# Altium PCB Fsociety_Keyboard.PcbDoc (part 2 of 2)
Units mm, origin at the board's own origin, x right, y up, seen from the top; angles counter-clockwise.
Board outline 368.7 x 110 mm, 2 copper layers (Top Layer, Bottom Layer), stack 1.601 mm thick; 249 components, 201 nets, 1088 pads, 275 vias.
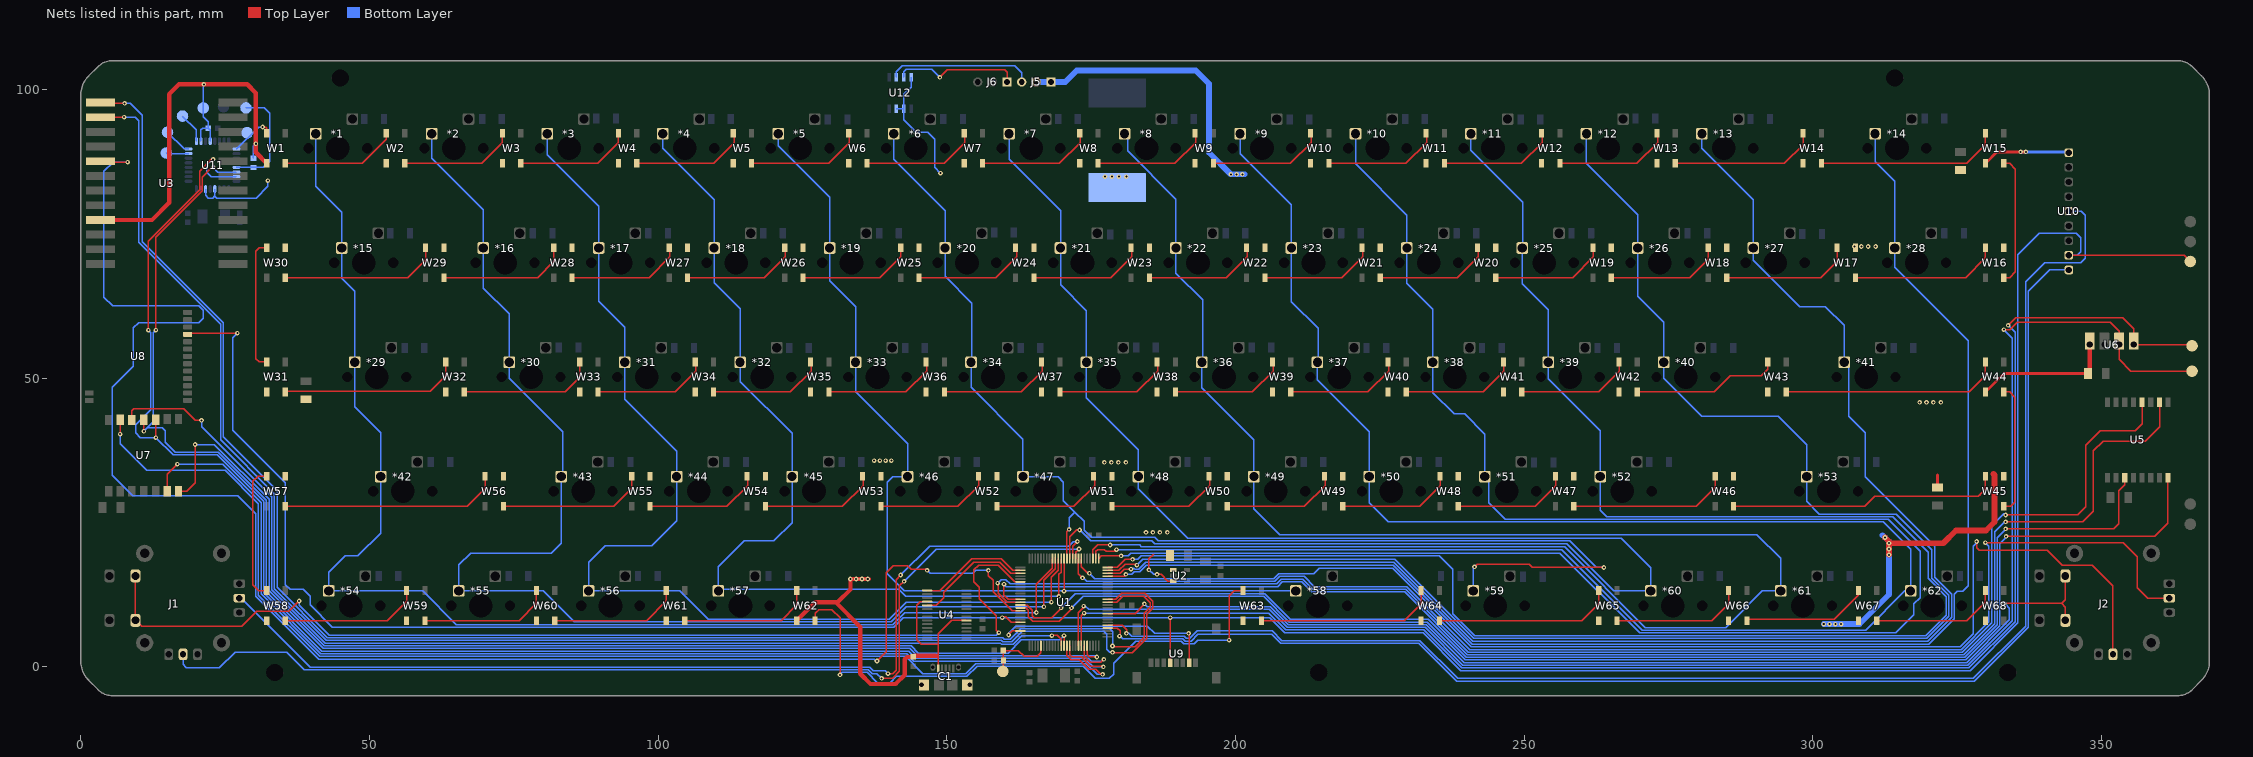
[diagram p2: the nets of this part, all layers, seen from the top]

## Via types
v1: diameter 0.8, hole 0.35, Top Layer to Bottom Layer, tented both sides, 275 vias

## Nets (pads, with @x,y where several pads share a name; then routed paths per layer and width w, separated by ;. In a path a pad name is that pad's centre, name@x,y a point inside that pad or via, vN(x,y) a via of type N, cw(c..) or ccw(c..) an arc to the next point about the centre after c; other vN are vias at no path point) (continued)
NetJ1_2: J1.2 U1.85 | length 172.5
  Top Layer w0.254: v1(139.8,-1.2) 140.6,-1.2 141.2,-0.6 141.2,15.1 v1(142,15.9) ; U1.85@171.8,18.75 171.8,20.9 v1(172.6,21.7)
  Bottom Layer w0.254: J1.2@27.45,11.9 27.8,11.9 39.771,-0.071 136.629,-0.071 137.258,-0.7 139.3,-0.7 v1(139.8,-1.2) ; v1(142,15.9) 147,20.9 171.1,20.9 171.9,21.7 v1(172.6,21.7)
NetJ1_5: J1.5 U1.84 | length 180.1
  Top Layer w0.254: v1(138.7,-2) 140.6,-2 141.8,-0.8 141.8,14 v1(142.6,14.8) ; U1.84@172.3,18.75 172.3,19.8 v1(172.9,20.4)
  Bottom Layer w0.254: J1.5@17.7,2.15 17.7,0.4 18.2,-0.1 18.2,-0.2 24,-0.2 26.7,2.5 35.7,2.5 38.725,-0.525 136.425,-0.525 137.1,-1.2 137.9,-1.2 v1(138.7,-2) ; v1(142.6,14.8) 148.2,20.4 v1(172.9,20.4)
NetJ2_2: J2.2 U1.83 | length 221.4
  Top Layer w0.254: U1.83@172.8,18.75 172.8,16.1 v1(173.5,15.4) v1@173.6,15.3 ; v1(329.9,21.5) 353.8,21.5 356.2,19.1 356.2,13.7 358,11.9 J2.2@361.75,11.9
  Bottom Layer w0.254: v1(173.5,15.4) 173.608,15.4 174.2,14.808 206.8,14.808 207.646,15.654 211.9,15.654 213.654,13.9 229.7,13.9 240.608,2.992 325.734,2.992 330.5,7.758 330.5,20.9 v1@330,21.4
NetJ2_5: J2.5 U1.82 | length 219.7
  Top Layer w0.254: U1.82@173.3,18.75 173.3,17.3 174.4,16.2 v1(174.7,16.2) v1@174.8,16.1 ; v1(328.4,21.7) 328.4,20.6 328.8,20.2 340.6,20.2 343.2,17.6 348.4,17.6 352,14 J2.5@352,2.15
  Bottom Layer w0.254: v1(174.7,16.2) 175.638,15.262 206.612,15.262 207.458,16.108 213.562,16.108 214.481,17.027 227.231,17.027 240.812,3.446 325.546,3.446 327.8,5.7 327.8,20.9 v1@328.5,21.6
NetJ2_7: J2.7 U1.59 | length 185.5
  Top Layer w0.254: U1.59@177.85,9.2 182.6,9.2 184.2,10.8 v1@184.3,10.8 ; v1(333.2,11) 343.1,11 ; J2.7@343.75,8.05 343.75,10.35 343.1,11 ; J2.7@343.75,15.75 343.75,11.65 343.1,11
  Bottom Layer w0.254: v1(184.2,10.9) 184.7,10.4 206.016,10.4 209.124,7.292 233.018,7.292 239.588,0.722 326.674,0.722 334.076,8.124 334.076,10.124 v1@333.3,10.9
NetJ5_3: J5.3 U12.6 | length 25.2
  Bottom Layer w0.254: U12.6@141.265,102.125 141.265,103.065 142.3,104.1 161.8,104.1 162.968,102.932 J5.3@162.968,101.3
NetJ6_1: J6.1 U12.7 | length 22
  Top Layer w0.254: v1(148.8,102.1) 150.1,103.4 160,103.4 160.44,102.96 J6.1@160.44,101.3
  Bottom Layer w0.254: U12.7@142.535,102.125 142.535,103.035 143,103.5 147.4,103.5 v1(148.8,102.1)
NetR2_2: R2.2 TP9.1 U11.29 | length 19
  Bottom Layer w0.254: U11.29@26.95,86.5 R2.2@29.9,86.5 31.6,86.5 32.7,87.6 32.7,95.9 31.8,96.8 TP9.1@28.6,96.8
NetTP10_1: TP10.1 U11.15 | length 3.9
  Bottom Layer w0.254: TP10.1@14.8,89 14.9,88.9 U11.15@18.65,88.9
NetTP11_1: TP11.1 U11.16 | length 4.9
  Bottom Layer w0.254: TP11.1@15,92.6 17.9,89.7 U11.16@18.65,89.7
NetTP12_1: TP12.1 U11.17 | length 5.3
  Bottom Layer w0.254: TP12.1@17.6,95.4 20,93 U11.17@20,91.05
NetTP13_1: TP13.1 U11.25 W1.4 | length 7.8
  Top Layer w0.254: v1(31.5,93.5) 32,93.5 32.21,93.29 W1.4@32.21,92.4
  Bottom Layer w0.254: U11.25@26.95,89.7 27,89.7 30.8,93.5 v1(31.5,93.5)
NetTP14_1: TP14.1 U1.43 U6.3 | length 265.9
  Top Layer w0.254: U1.43@172.8,3.65 172.8,9.4 v1@173.8,10.4 ; v1(333.1,58.4) 334.128,58.4 335.428,59.7 351.5,59.7 353.065,58.135 U6.3@353.065,55.825 353.065,53.235 355.1,51.2 TP14.1@365.7,51.2
  Bottom Layer w0.254: v1(173.7,10.5) 174,10.5 174.554,9.946 205.828,9.946 208.936,6.838 232.83,6.838 239.4,0.268 326.862,0.268 334.591,7.997 334.591,56.909 v1@333.2,58.3
NetTP15_1: TP15.1 U1.44 U6.4 | length 262.1
  Top Layer w0.254: U1.44@173.3,3.65 173.3,8.8 v1(173.8,9.3) ; v1(333.85,59.15) 335.2,60.5 353.7,60.5 355.605,58.595 U6.4@355.605,55.825 365.475,55.825 TP15.1@365.7,55.6
  Bottom Layer w0.254: v1(173.8,9.3) 205.8,9.3 208.716,6.384 232.642,6.384 239.212,-0.186 327.05,-0.186 335.045,7.809 335.045,57.955 v1@333.95,59.05
NetU1_2: U1.2 U4.1 | length 19.3
  Top Layer w0.254: U4.1@146.6,13.225 146.625,13.2 148.8,13.2 154.3,18.7 159.4,18.7 161.4,16.7 U1.2@162.75,16.7
NetU1_3: U1.3 U4.5 | length 20.6
  Top Layer w0.254: U4.5@146.6,10.625 148.125,10.625 149.5,12 149.5,12.9 154.7,18.1 159.2,18.1 161.1,16.2 U1.3@162.75,16.2
NetU1_12: U1.12 U5.2 | length 247.1
  Top Layer w0.254: v1@159.9,14.2 159.9,12.4 160.6,11.7 U1.12@162.75,11.7 ; v1(333.4,25.1) 346.8,25.1 348.6,26.9 348.6,37.4 350.3,39.1 357.6,39.1 360.1,41.6 U5.2@360.1,45.84
  Bottom Layer w0.254: v1(159.9,14.3) 160.3,13.9 207.3,13.9 208.1,14.7 211.5,14.7 213.244,12.956 213.265,12.977 229.281,12.977 240.174,2.084 326.11,2.084 331.492,7.466 331.492,23.392 v1@333.4,25.3
NetU1_13: U1.13 U5.4 | length 247
  Top Layer w0.254: v1@158.9,14.4 158.9,12.758 160.458,11.2 U1.13@162.75,11.2 ; v1(333.4,26.3) 345.9,26.3 347.3,27.7 347.3,38.4 349.8,40.9 355.9,40.9 357.1,42.1 U5.4@357.1,45.84
  Bottom Layer w0.254: v1(158.8,14.5) 159.4,15.1 160.2,15.1 160.946,14.354 207.112,14.354 207.958,15.2 211.642,15.2 213.396,13.446 229.454,13.446 240.362,2.538 325.922,2.538 331.038,7.654 331.038,24.438 333.1,26.5 v1@333.5,26.5
NetU1_14: U1.14 U5.11 | length 225
  Top Layer w0.254: U1.14@162.75,10.7 163.9,10.7 164.773,9.827 164.773,8.827 165.1,8.5 168.2,8.5 169.8,10.1 v1@169.9,10.1 ; v1(333.4,23.9) 352.1,23.9 353,24.8 353,30.5 354.05,31.55 U5.11@354.05,32.76
  Bottom Layer w0.254: v1(169.8,10.2) 172.254,12.654 205.046,12.654 209.5,8.2 233.4,8.2 239.97,1.63 326.298,1.63 331.946,7.278 331.946,22.346 v1@333.5,23.9
NetU1_15: U1.15 U5.16 | length 232.8
  Top Layer w0.254: U1.15@162.75,10.2 163.675,10.2 164.1,9.775 164.1,8.7 164.9,7.9 169.5,7.9 v1@171.7,10.1 ; v1(333.5,22.6) 359.2,22.6 361.5,24.9 U5.16@361.5,32.76
  Bottom Layer w0.254: v1(171.6,10.2) 173.6,12.2 204.858,12.2 209.312,7.746 233.212,7.746 239.782,1.176 326.486,1.176 332.4,7.09 332.4,21.3 v1@333.6,22.5
NetU1_23: U1.23 U9.2 | length 39.9
  Top Layer w0.254: v1@160.7,5.6 161.3,6.2 U1.23@162.75,6.2 ; v1(191.9,5.8) 191.975,5.725 U9.2@191.975,0.725
  Bottom Layer w0.254: v1(160.7,5.5) v1(160.7,5.5) 160.7,5.8 161.946,7.046 184.754,7.046 186,5.8 v1(191.9,5.8)
NetU1_37: U1.37 U7.12 | length 191.5
  Top Layer w0.254: U7.12@8.829,42.744 8.829,44.329 9.2,44.7 17.8,44.7 19.8,42.7 v1(20.9,42.7) ; v1@168.392,5.492 169.1,5.492 169.8,4.792 U1.37@169.8,3.65
  Bottom Layer w0.254: v1(20.9,42.7) 20.9,41.6 33.076,29.424 33.076,13.372 42.348,4.1 159.258,4.1 159.493,3.865 161.465,3.865 163,5.4 v1(168.2,5.4)
NetU1_38: U1.38 U7.7 | length 187.8
  Top Layer w0.254: U7.7@16.918,30.399 18.299,30.399 19.8,31.9 v1(19.8,38.5) ; U1.38@170.3,3.65 v1(170.3,5.4)
  Bottom Layer w0.254: v1(19.8,38.5) 23.122,38.5 32.6,29.022 32.6,13.2 42.154,3.646 143.8,3.646 145.073,2.373 160.615,2.373 162.915,4.673 169.573,4.673 v1(170.3,5.4)
NetU1_39: U1.39 U7.13 | length 211
  Top Layer w0.254: v1(6.8,40.3) 6.816,40.316 U7.13@6.816,42.794 ; U1.39@170.8,3.65 170.8,1.958 171.512,1.246 172.954,1.246 174.6,-0.4 175.8,-0.4 176.7,-1.3 v1(177,-1.3) v1@177.1,-1.3
  Bottom Layer w0.254: v1(6.8,40.3) 6.8,38.6 11.4,34 25,34 30.746,28.254 30.746,12.432 41.386,1.792 142.866,1.792 145.858,-1.2 153.3,-1.2 155.046,0.546 174.17,0.546 176.016,-1.3 v1(177,-1.3)
NetU1_40: U1.40 U7.6 | length 197.8
  Top Layer w0.254: U7.6@14.951,30.399 14.951,33.351 v1(16.7,35.1) ; U1.40@171.3,3.65 171.3,2.1 171.7,1.7 173.258,1.7 174.858,0.1 v1@177.1,0.1
  Bottom Layer w0.254: v1(16.7,35.1) 24.542,35.1 31.2,28.442 31.2,12.62 41.574,2.246 143.054,2.246 144.3,1 174.358,1 175.358,0 v1(177.1,0)
NetU1_63: U1.63 U3.0 | length 272.2
  Top Layer w0.254: U3.0@3.425,97.725 3.55,97.6 v1(7.594,97.6) ; U1.63@177.85,11.2 179.442,11.2 180.442,12.2 184.1,12.2 185.2,11.1 185.2,10.3 184.2,9.3 184.2,5.1 182.6,3.5 v1@178.8,3.5
  Bottom Layer w0.254: v1(7.594,97.6) 8.575,97.6 10.6,95.575 10.6,73.6 24.646,59.554 24.646,39.854 33.984,30.516 33.984,13.748 42.687,5.045 159.655,5.045 159.927,4.773 161.001,4.773 162.82,6.592 178.208,6.592 178.7,6.1 v1(178.7,3.6)
NetU1_64: U1.64 U3.1 | length 272.9
  Top Layer w0.254: U3.1@3.425,95.185 3.44,95.2 v1(7.5,95.2) ; U1.64@177.85,11.7 179.3,11.7 180.3,12.7 184.3,12.7 185.654,11.346 185.654,10.112 184.654,9.112 184.654,4.912 182.142,2.4 v1@178.8,2.4
  Bottom Layer w0.254: v1(7.5,95.2) 9.4,95.2 10.052,94.548 10.052,73.506 24.192,59.366 24.192,39.308 33.53,29.97 33.53,13.56 42.499,4.591 159.409,4.591 159.681,4.319 161.219,4.319 163.038,6.138 177.162,6.138 177.7,5.6 177.7,3 178.2,2.5 v1(178.7,2.5)
NetW1_2: W1.2 W2.4 | length 20.3
  Top Layer w0.254: W1.2@35.39,87.2 48.715,87.2 52.91,91.395 W2.4@52.91,92.4
NetW2_2: W2.2 W3.4 | length 20
  Top Layer w0.254: W2.2@56.09,87.2 69.415,87.2 73,90.785 W3.4@73,92.4
NetW3_2: W3.2 W4.4 | length 20
  Top Layer w0.254: W3.2@76.19,87.2 89.515,87.2 93.11,90.795 W4.4@93.11,92.4
NetW4_2: W4.2 W5.4 | length 20
  Top Layer w0.254: W4.2@96.29,87.2 109.615,87.2 113.21,90.795 W5.4@113.21,92.4
NetW5_2: W5.2 W6.4 | length 20
  Top Layer w0.254: W5.2@116.19,87.2 129.515,87.2 133.11,90.795 W6.4@133.11,92.4
NetW6_2: W6.2 W7.4 | length 20
  Top Layer w0.254: W6.2@136.19,87.2 149.515,87.2 153.11,90.795 W7.4@153.11,92.4
NetW7_2: W7.2 W8.4 | length 20
  Top Layer w0.254: W7.2@156.19,87.2 169.515,87.2 173.11,90.795 W8.4@173.11,92.4
NetW8_2: W8.2 W9.4 | length 20
  Top Layer w0.254: W8.2@176.19,87.2 189.515,87.2 193.11,90.795 W9.4@193.11,92.4
NetW9_2: W9.2 W10.4 | length 20
  Top Layer w0.254: W9.2@196.19,87.2 209.515,87.2 213.11,90.795 W10.4@213.11,92.4
NetW10_2: W10.2 W11.4 | length 20
  Top Layer w0.254: W10.2@216.19,87.2 229.515,87.2 233.11,90.795 W11.4@233.11,92.4
NetW11_2: W11.2 W12.4 | length 20
  Top Layer w0.254: W11.2@236.19,87.2 249.515,87.2 253.11,90.795 W12.4@253.11,92.4
NetW12_2: W12.2 W13.4 | length 20
  Top Layer w0.254: W12.2@256.19,87.2 269.515,87.2 273.11,90.795 W13.4@273.11,92.4
NetW13_2: W13.2 W14.4 | length 25.4
  Top Layer w0.254: W13.2@276.19,87.2 295.1,87.2 298.31,90.41 W14.4@298.31,92.4
NetW14_2: W14.2 W15.4 | length 31.7
  Top Layer w0.254: W14.2@301.49,87.2 326.7,87.2 329.91,90.41 W15.4@329.91,92.4
NetW15_2: W15.2 W16.4 | length 22.6
  Top Layer w0.254: W16.4@333.09,67.4 334.1,67.4 335.1,68.4 335.1,86.2 334.1,87.2 W15.2@333.09,87.2
NetW16_2: W16.2 W17.4 | length 25.7
  Top Layer w0.254: W17.4@307.39,67.4 326.5,67.4 329.91,70.81 W16.2@329.91,72.6
NetW17_2: W17.2 W18.4 | length 22.7
  Top Layer w0.254: W18.4@285.09,67.4 301.4,67.4 304.21,70.21 W17.2@304.21,72.6
NetW18_2: W18.2 W19.4 | length 20.1
  Top Layer w0.254: W19.4@265.09,67.4 278.7,67.4 281.91,70.61 W18.2@281.91,72.6
NetW19_2: W19.2 W20.4 | length 20.1
  Top Layer w0.254: W20.4@245.09,67.4 258.415,67.4 262.01,70.995 262.01,72.5 W19.2@261.91,72.6
NetW20_2: W20.2 W21.4 | length 20
  Top Layer w0.254: W21.4@225.09,67.4 238.415,67.4 242.01,70.995 W20.2@242.01,72.6
NetW21_2: W21.2 W22.4 | length 20
  Top Layer w0.254: W22.4@205.09,67.4 218.415,67.4 222.01,70.995 W21.2@222.01,72.6
NetW22_2: W22.2 W23.4 | length 20
  Top Layer w0.254: W23.4@185.09,67.4 198.415,67.4 202.01,70.995 W22.2@202.01,72.6
NetW23_2: W23.2 W24.4 | length 20
  Top Layer w0.254: W24.4@165.09,67.4 178.415,67.4 182.01,70.995 W23.2@182.01,72.6
NetW24_2: W24.2 W25.4 | length 20
  Top Layer w0.254: W25.4@145.19,67.4 158.515,67.4 162.11,70.995 W24.2@162.11,72.6
NetW25_2: W25.2 W26.4 | length 20
  Top Layer w0.254: W26.4@125.09,67.4 138.415,67.4 142.01,70.995 W25.2@142.01,72.6
NetW26_2: W26.2 W27.4 | length 20
  Top Layer w0.254: W27.4@105.09,67.4 118.415,67.4 122.01,70.995 W26.2@122.01,72.6
NetW27_2: W27.2 W28.4 | length 20
  Top Layer w0.254: W28.4@85.09,67.4 98.415,67.4 102.01,70.995 W27.2@102.01,72.6
NetW28_2: W28.2 W29.4 | length 22.6
  Top Layer w0.254: W29.4@62.89,67.4 79.1,67.4 81.91,70.21 W28.2@81.91,72.6
NetW29_2: W29.2 W30.4 | length 27.7
  Top Layer w0.254: W30.4@35.39,67.4 56.6,67.4 59.71,70.51 W29.2@59.71,72.6
NetW30_2: W30.2 W31.4 | length 22.9
  Top Layer w0.254: W31.4@32.21,52.8 30.9,52.8 30.3,53.4 30.3,72 30.9,72.6 W30.2@32.21,72.6
NetW31_2: W31.2 W32.4 | length 31.4
  Top Layer w0.254: W31.2@35.39,47.6 35.49,47.7 60.5,47.7 63.21,50.41 W32.4@63.21,52.8
NetW32_2: W32.2 W33.4 | length 23.7
  Top Layer w0.254: W32.2@66.39,47.6 83.9,47.6 86.41,50.11 W33.4@86.41,52.8
NetW33_2: W33.2 W34.4 | length 20
  Top Layer w0.254: W33.2@89.59,47.6 102.915,47.6 106.51,51.195 W34.4@106.51,52.8
NetW34_2: W34.2 W35.4 | length 20
  Top Layer w0.254: W34.2@109.59,47.6 122.915,47.6 126.51,51.195 W35.4@126.51,52.8
NetW35_2: W35.2 W36.4 | length 20
  Top Layer w0.254: W35.2@129.59,47.6 142.915,47.6 146.51,51.195 W36.4@146.51,52.8
NetW36_2: W36.2 W37.4 | length 20
  Top Layer w0.254: W36.2@149.59,47.6 162.915,47.6 166.51,51.195 W37.4@166.51,52.8
NetW37_2: W37.2 W38.4 | length 20
  Top Layer w0.254: W37.2@169.59,47.6 182.915,47.6 186.51,51.195 W38.4@186.51,52.8
NetW38_2: W38.2 W39.4 | length 20
  Top Layer w0.254: W38.2@189.59,47.6 202.915,47.6 206.51,51.195 W39.4@206.51,52.8
NetW39_2: W39.2 W40.4 | length 20
  Top Layer w0.254: W39.2@209.59,47.6 222.915,47.6 226.51,51.195 W40.4@226.51,52.8
NetW40_2: W40.2 W41.4 | length 20
  Top Layer w0.254: W40.2@229.59,47.6 242.915,47.6 246.51,51.195 W41.4@246.51,52.8
NetW41_2: W41.2 W42.4 | length 20
  Top Layer w0.254: W41.2@249.59,47.6 262.915,47.6 266.51,51.195 W42.4@266.51,52.8
NetW42_2: W42.2 W43.4 | length 25.5
  Top Layer w0.254: W42.2@269.59,47.6 282.915,47.6 285.715,50.4 291.1,50.4 292.21,51.51 W43.4@292.21,52.8
NetW43_2: W43.2 W44.4 | length 38.1
  Top Layer w0.254: W43.2@295.39,47.6 327.1,47.6 329.91,50.41 W44.4@329.91,52.8
NetW44_2: W44.2 W45.4 | length 22.7
  Top Layer w0.254: W45.4@333.09,27.8 334.3,27.8 335,28.5 335,46.7 334.1,47.6 W44.2@333.09,47.6
NetW45_2: W45.2 W46.4 | length 47.5
  Top Layer w0.254: W46.4@286.29,27.8 309,27.8 310.7,29.5 328.7,29.5 ; 329,29.8 328.7,29.5 ; W45.2@329.91,33 329.91,30.71 328.7,29.5
NetW46_2: W46.2 W47.4 | length 27.8
  Top Layer w0.254: W47.4@258.59,27.8 279.8,27.8 283.11,31.11 W46.2@283.11,33
NetW47_2: W47.2 W48.4 | length 20
  Top Layer w0.254: W48.4@238.59,27.8 251.915,27.8 255.51,31.395 W47.2@255.51,33
NetW48_2: W48.2 W49.4 | length 20
  Top Layer w0.254: W49.4@218.59,27.8 231.915,27.8 235.51,31.395 W48.2@235.51,33
NetW49_2: W49.2 W50.4 | length 20
  Top Layer w0.254: W50.4@198.59,27.8 211.915,27.8 215.51,31.395 W49.2@215.51,33
NetW50_2: W50.2 W51.4 | length 20
  Top Layer w0.254: W51.4@178.59,27.8 191.915,27.8 195.51,31.395 W50.2@195.51,33
NetW51_2: W51.2 W52.4 | length 20
  Top Layer w0.254: W52.4@158.69,27.8 172.015,27.8 175.61,31.395 W51.2@175.61,33
NetW52_2: W52.2 W53.4 | length 20
  Top Layer w0.254: W53.4@138.59,27.8 151.915,27.8 155.51,31.395 W52.2@155.51,33
NetW53_2: W53.2 W54.4 | length 20
  Top Layer w0.254: W54.4@118.59,27.8 131.915,27.8 135.51,31.395 W53.2@135.51,33
NetW54_2: W54.2 W55.4 | length 20.1
  Top Layer w0.254: W55.4@98.59,27.8 111.915,27.8 115.51,31.395 115.51,32.9 W54.2@115.41,33
NetW55_2: W55.2 W56.4 | length 25.6
  Top Layer w0.254: W56.4@73.19,27.8 92.3,27.8 95.41,30.91 W55.2@95.41,33
NetW56_2: W56.2 W57.4 | length 38
  Top Layer w0.254: W57.4@35.39,27.8 66.9,27.8 70.01,30.91 W56.2@70.01,33
NetW57_2: W57.2 W58.4 | length 23.5
  Top Layer w0.254: W58.4@32.21,13.2 30.8,13.2 29.8,14.2 29.8,32.1 30.7,33 W57.2@32.21,33
NetW58_2: W58.2 W59.4 | length 24.3
  Top Layer w0.254: W58.2@35.39,8 53.1,8 56.41,11.31 W59.4@56.41,13.2
NetW59_2: W59.2 W60.4 | length 22.8
  Top Layer w0.254: W59.2@59.59,8 75.9,8 78.91,11.01 W60.4@78.91,13.2
NetW60_2: W60.2 W61.4 | length 22.5
  Top Layer w0.254: W60.2@82.09,8 98,8 101.41,11.41 W61.4@101.41,13.2
NetW61_2: W61.2 W62.4 | length 23
  Top Layer w0.254: W61.2@104.59,8 121.3,8 124.01,10.71 W62.4@124.01,13.2
NetW62_2: W62.2 W63.4 | length 101.3
  Top Layer w0.254: W62.2@127.19,8 127.19,9.29 127.8,9.9 130.1,9.9 131.5,8.5 v1(131.5,-1.4) ; v1(198.9,4.6) 198.9,12.3 199.8,13.2 W63.4@201.31,13.2
  Bottom Layer w0.254: v1(131.5,-1.4) 131.921,-0.979 136.179,-0.979 137.927,-2.727 140.173,-2.727 141.246,-1.654 153.488,-1.654 155.234,0.092 173.608,0.092 175.727,-2.027 178.173,-2.027 178.9,-1.3 178.9,0.6 182.692,4.392 190.6,4.392 191,3.992 192.892,3.992 193.5,4.6 v1(198.9,4.6)
NetW63_2: W63.2 W64.4 | length 31.1
  Top Layer w0.254: W63.2@204.49,8 229.2,8 232.16,10.96 W64.4@232.16,13.2
NetW64_2: W64.2 W65.4 | length 31.1
  Top Layer w0.254: W64.2@235.34,8 260,8 262.91,10.91 W65.4@262.91,13.2
NetW65_2: W65.2 W66.4 | length 22.8
  Top Layer w0.254: W65.2@266.09,8 282.5,8 285.41,10.91 W66.4@285.41,13.2
NetW66_2: W66.2 W67.4 | length 21.9
  Top Layer w0.254: W66.2@288.59,8 288.79,8.2 303.7,8.2 307.91,12.41 W67.4@307.91,13.2
NetW67_2: W67.2 W68.4 | length 22.1
  Top Layer w0.254: W67.2@311.09,8 326.7,8 329.91,11.21 W68.4@329.91,13.2
NewNet1: C1.@153.975,-3.127 C1.Z6
NewNet2: C1.@145.625,-3.127 C1.Z3
NFCCS: U1.54 U10.1 | length 235.6
  Top Layer w0.254: U1.54@177.85,6.7 179.5,6.7 180,6.2 v1@180,5.2
  Bottom Layer w0.254: v1(179.9,5.3) 180,5.3 180.454,4.846 190.9,4.846 191.3,4.446 192.346,4.446 193.5,5.6 206.29,5.6 207.806,4.084 231.732,4.084 238.286,-2.47 327.996,-2.47 337.315,6.849 337.315,65.015 341.04,68.74 U10.1@344.35,68.74
NFCIRQ: U1.55 U10.5 | length 250.2
  Top Layer w0.254: U1.55@177.85,7.2 180.4,7.2 181.2,6.4 v1@181.2,5.7
  Bottom Layer w0.254: v1@181.392,5.9 181.992,5.3 191.1,5.3 191.5,4.9 192.1,4.9 193.4,6.2 206.332,6.2 207.994,4.538 231.92,4.538 238.474,-2.016 327.808,-2.016 336.861,7.037 336.861,66.661 340.2,70 346.4,70 347.2,70.8 347.2,78.2 346.5,78.9 U10.5@344.35,78.9
  other v1: 181.1,5.8
PAIRHID: U1.16 U3.4 | length 290
  Top Layer w0.254: U3.4@3.425,87.565 3.59,87.4 v1(8.1,87.4) ; v1(137.9,1) 139.546,2.646 139.546,16.33 140.751,17.535 143.165,17.535 143.8,16.9 146.4,16.9 v1(146.6,16.7) ; v1(157.2,16.7) 157.2,15.8 158,15 158,13 161.3,9.7 U1.16@162.75,9.7
  Bottom Layer w0.254: v1@8,87.6 8,87.4 5.6,87.4 4,85.8 4,64 5.5,62.5 20.416,62.5 21.2,61.716 21.2,60.4 20.4,59.6 10,59.6 9.1,58.7 9.1,52.1 5.4,48.4 5.4,33.2 8.98,29.62 27.181,29.62 30.292,26.509 30.292,12.244 41.198,1.338 137.4,1.338 137.738,1 v1(137.9,1) ; v1(146.6,16.7) 147.1,16.2 154.5,16.2 155,16.7 v1(157.2,16.7)
R1: *1.1 *15.1 *29.1 *42.1 *54.1 U1.92 | length 225.2
  Top Layer w0.254: v1(165.5,9.4) 165.5,14.296 168.3,17.096 U1.92@168.3,18.75
  Bottom Layer w0.254: *1.1@40.69,92.34 40.69,83.21 45.19,78.71 *15.1@45.19,72.54 45.19,67.31 47.44,65.06 *29.1@47.44,52.74 47.44,45.06 51.94,40.56 *42.1@51.94,32.94 51.94,23.14 48,19.2 45.8,19.2 42.94,16.34 *54.1@42.94,13.14 59.176,13.14 65.001,7.315 140.615,7.315 142.7,9.4 v1(165.5,9.4)
R2: *2.1 *16.1 *30.1 *43.1 *55.1 U1.91 | length 218.4
  Top Layer w0.254: v1(166.8,10.4) 166.8,14.954 168.823,16.977 U1.91@168.823,19
  Bottom Layer w0.254: *2.1@60.79,92.34 60.79,88.11 69.7,79.2 69.7,72.55 *16.1@69.69,72.54 69.69,65.61 74.19,61.11 *30.1@74.19,52.74 74.19,50.01 83.5,40.7 83.5,33.25 *43.1@83.19,32.94 83.19,21.39 81.5,19.7 67.5,19.7 65.44,17.64 *55.1@65.44,13.14 80.06,13.14 85.431,7.769 140.369,7.769 143,10.4 v1(166.8,10.4)
R3: *3.1 *17.1 *31.1 *44.1 *56.1 U1.90 | length 191
  Top Layer w0.254: v1(168.1,11.2) 168.1,15.5 169.3,16.7 U1.90@169.3,18.75
  Bottom Layer w0.254: *3.1@80.79,92.34 80.79,88.71 89.69,79.81 *17.1@89.69,72.54 89.69,63.31 94.19,58.81 *31.1@94.19,52.74 94.19,46.31 103.19,37.31 *44.1@103.19,32.94 103.19,25.29 98.9,21 90.8,21 87.94,18.14 *56.1@87.94,13.14 103.76,13.14 108.677,8.223 140.023,8.223 143,11.2 v1(168.1,11.2)
R4: *4.1 *18.1 *32.1 *45.1 *57.1 U1.89 | length 163
  Top Layer w0.254: v1(169.4,12.2) 169.4,16 169.8,16.4 U1.89@169.8,18.75
  Bottom Layer w0.254: *4.1@100.79,92.34 100.79,89.81 109.69,80.91 *18.1@109.69,72.54 109.69,66.51 114.19,62.01 *32.1@114.19,52.74 114.19,49.41 123.19,40.41 *45.1@123.19,32.94 123.19,24.99 120,21.8 114.9,21.8 110.44,17.34 *57.1@110.44,13.14 110.7,13.4 141.7,13.4 142.9,12.2 v1(169.4,12.2)
R5: *5.1 *19.1 *33.1 *46.1 *58.1 U1.88 | length 166.1
  Top Layer w0.254: v1(170.3,13.1) U1.88@170.3,18.75
  Bottom Layer w0.254: *5.1@120.79,92.34 120.79,90.248 129.69,81.348 *19.1@129.69,72.54 129.69,66.91 134.2,62.4 134.2,52.75 *33.1@134.19,52.74 134.19,47.61 143.19,38.61 *46.1@143.19,32.94 140.64,32.94 139.7,32 139.7,16.1 142.66,13.14 *58.1@210.44,13.14
R6: *6.1 *20.1 *34.1 *47.1 *59.1 U1.87 | length 214.1
  Top Layer w0.254: U1.87@170.8,18.75 170.8,23.4 v1(171.2,23.8) ; v1@241.6,17.5 241.9,17.8 250.846,17.8 251.446,17.2 v1(263.8,17.2)
  Bottom Layer w0.254: *6.1@140.79,92.34 140.79,87.91 149.69,79.01 *20.1@149.69,72.54 149.69,67.61 154.3,63 154.3,52.85 *34.1@154.19,52.74 154.19,48.41 163.19,39.41 *47.1@163.19,32.94 169.26,32.94 170.2,32 170.2,28.8 172.2,26.8 ; v1(171.2,23.8) 171.2,25.8 172.2,26.8 ; *59.1@241.19,13.14 241.19,17.09 v1(241.4,17.3) ; v1(263.8,17.2) 262.5,17.2 257.9,21.8 186.6,21.8 186,22.4 175.072,22.4 173.8,23.672 173.8,25.2 172.2,26.8
R7: *7.1 *21.1 *35.1 *48.1 *60.1 U1.86 | length 278.5
  Top Layer w0.254: U1.86@171.3,18.75 171.3,22.5 172.5,23.7 v1(173,23.7)
  Bottom Layer w0.254: *7.1@160.79,92.34 160.79,87.91 169.7,79 169.7,72.55 *21.1@169.69,72.54 169.69,66.21 174.19,61.71 *35.1@174.19,52.74 174.19,46.61 183.19,37.61 *48.1@183.19,32.94 183.19,30.848 191.738,22.3 257.758,22.3 257.765,22.307 258.035,22.307 258.042,22.3 266.8,22.3 271.94,17.16 *60.1@271.94,13.14 265.56,13.14 257.4,21.3 186,21.3 185.473,21.827 177.999,21.827 177.972,21.8 174.9,21.8 v1(173,23.7)
R8: *8.1 *22.1 *36.1 *49.1 *61.1 U1.78 | length 304.9
  Top Layer w0.254: U1.78@175.3,18.75 175.3,20.3 176.1,21.1 v1(178.3,21.1)
  Bottom Layer w0.254: v1(178.3,21.1) 183.4,21.1 183.7,20.8 257,20.8 271,6.8 ; *8.1@180.79,92.34 181.3,91.83 181.3,89.4 189.69,81.01 *22.1@189.69,72.54 189.69,68.21 194.3,63.6 194.3,52.85 *36.1@194.19,52.74 194.19,48.31 203.19,39.31 *49.1@203.19,32.94 203.19,27.41 207.7,22.9 290.3,22.9 294.44,18.76 *61.1@294.44,13.14 291.24,13.14 284.9,6.8 271,6.8 ; 271.6,6.8 271,6.8
R9: *9.1 *23.1 *37.1 *50.1 *62.1 U1.77 | length 329
  Top Layer w0.254: U1.77@175.8,18.75 175.8,20 176.1,20.3 177.3,20.3 177.6,20 179.1,20 v1(179.4,20.3)
  Bottom Layer w0.254: v1(179.4,20.3) 256.546,20.3 270.5,6.346 309.146,6.346 315.94,13.14 *62.1@316.94,13.14 316.94,20.36 312.2,25.1 226.5,25.1 223.19,28.41 *50.1@223.19,32.94 223.19,40.71 214.19,49.71 *37.1@214.19,52.74 214.3,52.85 214.3,58.6 209.69,63.21 *23.1@209.69,72.54 209.69,80.01 200.79,88.91 *9.1@200.79,92.34
R10: *10.1 *24.1 *38.1 *51.1 U1.76 | length 312.8
  Top Layer w0.254: U1.76@176.3,18.75 176.75,19.2 v1(180.2,19.2)
  Bottom Layer w0.254: v1(180.2,19.2) 181.4,19.2 181.9,19.7 256.2,19.7 270.008,5.892 314.392,5.892 317.5,9 317.5,10.9 318.6,12 318.6,20 313.046,25.554 246.746,25.554 243.9,28.4 243.9,32.23 *51.1@243.19,32.94 243.19,40.31 239.7,43.8 237.9,43.8 234.19,47.51 *38.1@234.19,52.74 234.2,52.75 234.2,61.9 229.69,66.41 *24.1@229.69,72.54 229.69,78.21 220.79,87.11 *10.1@220.79,92.34
R11: *11.1 *25.1 *39.1 *52.1 U1.75 | length 304.4
  Top Layer w0.254: U1.75@177.85,17.2 179.5,17.2 180.9,18.6 v1(182.2,18.6)
  Bottom Layer w0.254: v1(182.2,18.6) 183.1,18.6 183.7,19.2 235.3,19.2 237.6,16.9 237.6,9.226 241.426,5.4 319.6,5.4 323.127,8.927 323.127,12.173 320,15.3 320,19.842 313.834,26.008 264.292,26.008 263.19,27.11 *52.1@263.19,32.94 263.19,40.91 254.19,49.91 *39.1@254.19,52.74 254.19,61.81 249.69,66.31 *25.1@249.69,72.54 249.8,72.65 249.8,80.5 240.79,89.51 *11.1@240.79,92.34
R12: *12.1 *26.1 *40.1 *53.1 U1.74 | length 279.1
  Top Layer w0.254: U1.74@177.85,16.7 179.8,16.7 180.9,17.8 182.7,17.8 v1(182.9,17.6)
  Bottom Layer w0.254: v1(182.9,17.6) 183.9,18.6 227.584,18.6 241.284,4.9 319.742,4.9 323.581,8.739 323.581,12.361 320.6,15.342 320.6,20.3 314.438,26.462 301.138,26.462 298.94,28.66 *53.1@298.94,32.94 298.94,38.46 294,43.4 280.8,43.4 274.19,50.01 *40.1@274.19,52.74 274.19,59.71 269.69,64.21 *26.1@269.69,72.54 269.69,78.31 260.79,87.21 *12.1@260.79,92.34
R13: *13.1 *27.1 *41.1 U1.73 | length 258.9
  Top Layer w0.254: U1.73@177.85,16.2 180,16.2 180.7,16.9 v1(181.9,16.9)
  Bottom Layer w0.254: v1(181.9,16.9) 182.082,17.082 182.39,17.082 182.599,16.873 183.201,16.873 184.428,18.1 227.442,18.1 241.142,4.4 319.884,4.4 324.035,8.551 324.035,12.573 321.1,15.508 321.1,20.9 309.1,32.9 309.1,40.5 306.2,43.4 306.2,51.98 *41.1@305.44,52.74 305.44,59.16 302.2,62.4 297.738,62.4 289.69,70.448 *27.1@289.69,72.54 289.69,80.91 280.79,89.81 *13.1@280.79,92.34
R14: *14.1 *28.1 U1.72 | length 246.8
  Top Layer w0.254: U1.72@177.85,15.7 180.7,15.7 v1(181,16)
  Bottom Layer w0.254: 181.4,16 182.028,16 182.447,16.419 183.389,16.419 184.57,17.6 227.3,17.6 241,3.9 320.1,3.9 324.489,8.289 324.489,12.589 325,13.1 326,13.1 326.9,14 326.9,56.5 314.19,69.21 *28.1@314.19,72.54 314.19,84.083 310.79,87.483 *14.1@310.79,92.34
RESET: C6.2 R1.1 TP6.1 U1.30 | length 12.1
  Top Layer w0.254: TP6.1@159.7,-0.8 159.8,-0.7 R1.1@159.8,1.1 C6.2@159.8,2.8 162.4,2.8 163.4,1.8 165.7,1.8 166.3,2.4 U1.30@166.3,3.65
RXW: U1.45 U7.10 U11.31 | length 264.2
  Top Layer w0.254: v1(11.7,58.3) 11.7,73.7 12.546,74.546 12.546,74.588 20.562,82.604 20.562,85.862 22.6,87.9 v1(22.9,87.9) ; U7.10@12.944,42.794 13,42.739 v1(13,39.7) ; U1.45@173.8,3.65 173.8,1.8 174.8,0.8 176.7,0.8 v1(177.2,1.3)
  Bottom Layer w0.254: v1(11.7,58.3) 12.1,57.9 12.1,44.5 9.5,41.9 9.5,40.5 10.3,39.7 v1(13,39.7) 16,36.7 23.584,36.7 31.654,28.63 31.654,12.808 41.762,2.7 143.4,2.7 144.635,1.465 174.535,1.465 175.027,0.973 176.873,0.973 v1(177.2,1.3) ; v1(22.9,87.9) 22.7,87.9 21.8,87 21.8,85.7 22.6,84.9 U11.31@26.95,84.9
SCK: TP1.1 U1.20 U8.10 U9.5 U10.2 | length 482.4
  Top Layer w0.254: U8.10@18.475,57.575 18.7,57.8 v1(27.1,57.8) ; v1@159.6,8.7 160.2,8.7 161.2,7.7 U1.20@162.75,7.7 ; U9.5@188.675,0.725 188.675,8.475 v1(188.7,8.5) ; U10.2@344.35,71.28 364.32,71.28 TP1.1@365.4,70.2
  Bottom Layer w0.254: v1(27.1,57.8) 26.3,57 26.3,41 35.408,31.892 35.408,14.25 36.25,13.408 38.476,13.408 39.708,12.176 39.708,10.734 43.581,6.861 140.803,6.861 142.442,8.5 v1(159.6,8.5) v1(188.7,8.5) 205.958,8.5 208.558,5.9 232.484,5.9 239.038,-0.654 327.244,-0.654 335.499,7.601 335.499,71.399 339.2,75.1 345.6,75.1 346.4,74.3 346.4,71.9 345.78,71.28 U10.2@344.35,71.28
SJ1: J1.7 U1.6 | length 184.8
  Top Layer w0.254: J1.7@9.45,15.75 J1.7@9.45,8.05 10.5,7 27.9,7 30.5,9.6 36,9.6 v1(37.8,11.4) ; v1(159,5.9) 158.6,6.3 158.6,8.8 155.6,11.8 155.6,13.8 154.673,14.727 154.673,16.773 155.5,17.6 158.9,17.6 161.8,14.7 U1.6@162.75,14.7
  Bottom Layer w0.254: v1(37.8,11.4) 37.8,10.699 39.4,9.099 43,5.499 158.599,5.499 v1(159,5.9)
TXW: U1.46 U7.11 U11.30 | length 252.1
  Top Layer w0.254: U7.11@10.861,42.794 10.861,40.839 v1(10.9,40.8) ; v1(13,58.3) 13,74.4 21.016,82.416 21.016,84.816 22.7,86.5 v1(22.9,86.5) ; U1.46@174.3,3.65 174.3,2.1 174.7,1.7 v1(176,1.7)
  Bottom Layer w0.254: v1(10.9,40.8) 11.5,41.4 ; v1(13,58.3) 12.554,57.854 12.554,42.454 11.5,41.4 ; 14.2,41.4 14.1,41.4 ; v1(22.9,86.5) 23.7,85.7 U11.30@26.95,85.7 ; v1(176,1.7) 175.781,1.919 144.885,1.919 143.704,3.1 143.692,3.1 143.6,3.192 41.966,3.192 32.146,13.012 32.146,28.834 23.826,37.154 16.346,37.154 14.6,38.9 14.6,40.9 14.1,41.4 ; 11.5,41.4 14.1,41.4
VCC: C1.1 C9.1 C11.1 C13.1 C14.1 C15.1 C19.1 C20.2 J3.1 J5.1 J5.2 R2.1 TP8.1 U2.1 U2.3 U3.8 U4.4 U4.20 U6.1 U10.9 U11.4 U11.6 U11.18 U11.20 U12.2 U12.3 U12.8 W1.1 W2.1 W3.1 W4.1 W5.1 W6.1 W7.1 W8.1 W9.1 W10.1 W11.1 W12.1 W13.1 W14.1 W15.1 W16.1 W17.1 W18.1 W19.1 W20.1 W21.1 W22.1 W23.1 W24.1 W25.1 W26.1 W27.1 W28.1 W29.1 W30.1 W31.1 W32.1 W33.1 W34.1 W35.1 W36.1 W37.1 W38.1 W39.1 W40.1 W41.1 W42.1 W43.1 W44.1 W45.1 W46.1 W47.1 W48.1 W49.1 W50.1 W51.1 W52.1 W53.1 W54.1 W55.1 W56.1 W57.1 W58.1 W59.1 W60.1 W61.1 W62.1 W63.1 W64.1 W65.1 W66.1 W67.1 W68.1 | length 346.8
  Top Layer w0.254: U4.4@146.6,11.275 145.375,11.275 144.8,10.7 144.8,4.7 145.6,3.9 148.5,3.9 ; C1.1@148.5,-0.322 148.5,1.5 ; 148.5,2.9 148.5,2.3 ; U4.20@153.4,8.025 150.825,8.025 148.5,5.7 148.5,3.9 ; v1(185,16.8) 185,18.7 185.8,19.5 ; v1(186.4,16) 187.146,16 188.296,14.85 U2.3@189.2,14.85 ; 148.5,1.5 148.5,2.3 ; 148.5,1.5 148.1,1.9 148.5,2.3 ; 148.5,2.3 148.5,3.9
  Top Layer w0.5: C11.1@321.6,31.05 321.6,33.2 ; W44.1@329.91,47.6 333.11,50.8 C14.1@347.65,50.8 ; W15.1@329.91,87.2 331.91,89.2 v1(336,89.2) v1(336.9,89.2)
  Top Layer w0.75: U3.8@3.425,77.405 12.305,77.405 15.3,80.4 15.3,99.2 17,100.9 28.8,100.9 30.3,99.4 30.3,89.11 W1.1@32.21,87.2 ; W62.1@124.01,8 127.21,11.2 130.7,11.2 ; v1@136.5,15.2 v1(133.3,15.2) 133.3,13.4 131.1,11.2 130.7,11.2 ; 148.1,1.9 144.4,1.9 C20.2@144.2,1.7 143.1,1.7 142.7,1.3 142.7,-1.4 141.125,-2.975 136.775,-2.975 135,-1.2 135,6.9 130.7,11.2 ; C14.1@347.65,50.8 347.985,51.135 U6.1@347.985,55.825
  Top Layer w1: v1(312.5,22.4) 313.2,21.7 v1(313.2,21.4) ; v1(313.2,19.4) v1(313.2,20.4) v1(313.2,21.4) ; 331.3,33.4 331.5,33.2 331.5,25.1 330,23.6 324.8,23.6 322.6,21.4 v1(313.2,21.4)
  Bottom Layer w0.254: U11.18@20.8,91.05 20.8,93 21.1,93.3 C19.1@22.1,93.3 ; v1(21.3,100.9) 21.2,100.8 TP8.1@21.2,96.8 21.2,95.3 22.1,94.4 C19.1@22.1,93.3 ; U11.6@21.6,82.75 21.6,81.7 22.1,81.2 22.8,81.2 23.2,81.6 ; U11.20@22.4,91.05 22.4,93 C19.1@22.1,93.3 ; U11.4@23.2,82.75 23.2,81.6 ; R2.1@29.9,88.1 29.9,90.2 v1(30.3,90.6) ; v1(32.4,84.2) 32.4,83.2 30.4,81.2 23.5,81.2 23.2,81.5 23.2,81.6 ; U12.3@141.265,96.675 U12.2@142.535,96.675 ; U12.8@143.805,102.125 143.805,100.405 142.535,99.135 U12.2@142.535,96.675 ; v1(148.9,85.5) 147.9,86.5 147.9,91.4 146.7,92.6 144.7,92.6 142.535,94.765 U12.2@142.535,96.675 ; v1(185,16.8) 185.8,16 v1(186.4,16)
  Bottom Layer w0.5: v1(336,89.2) v1(336.9,89.2) 344.21,89.2 U10.9@344.35,89.06
  Bottom Layer w1: J5.2@165.508,101.3 J5.1@168.048,101.3 170.5,101.3 172.5,103.3 193.1,103.3 195.4,101 195.4,89.1 v1(199.2,85.3) 201.6,85.3 ; v1(301.9,7.4) v1(302.9,7.4) v1(303.9,7.4) v1(304.9,7.4) 308.1,7.4 313.2,12.5 v1(313.2,19.4) v1(313.2,20.4) v1(313.2,21.4) 313.2,21.7 v1(312.5,22.4) 312.1,22.8
  other v1: 134.3,15.2 135.3,15.2 136.3,15.2 184.5,23.3 185.7,23.3 186.9,23.3 188.2,23.3 177.3,35.4 178.5,35.4 179.7,35.4 181,35.4 137.4,35.7 138.4,35.7 139.4,35.7 140.4,35.7 318.5,45.8 319.7,45.8 320.9,45.8 322.2,45.8 307.2,72.8 308.4,72.8 309.6,72.8 310.9,72.8 177.4,84.9 178.6,84.9 179.8,84.9 181.1,84.9 200.2,85.3 201.2,85.3
pads on no net: *1.0 *2.0 *3.0 *4.0 *5.0 *6.0 *7.0 *8.0 *9.0 *10.0 *11.0 *12.0 *13.0 *14.0 *15.0 *16.0 *17.0 *18.0 *19.0 *20.0 *21.0 *22.0 *23.0 *24.0 *25.0 *26.0 *27.0 *28.0 *29.0 *30.0 *31.0 *32.0 *33.0 *34.0 *35.0 *36.0 *37.0 *38.0 *39.0 *40.0 *41.0 *42.0 *43.0 *44.0 *45.0 *46.0 *47.0 *48.0 *49.0 *50.0 *51.0 *52.0 *53.0 *54.0 *55.0 *56.0 *57.0 *58.0 *59.0 *60.0 *61.0 *62.0 C1.4 C1.Z4 C1.Z5 J1.0 J2.0 U1.1 U1.4 U1.5 U1.7 U1.8 U1.9 U1.19 U1.24 U1.25 U1.26 U1.27 U1.28 U1.29 U1.35 U1.36 U1.41 U1.42 U1.47 U1.48 U1.49 U1.50 U1.51 U1.52 U1.53 U1.56 U1.57 U1.58 U1.60 U1.65 U1.66 U1.67 U1.68 U1.69 U1.70 U1.79 U2.4 U3.2 U3.3 U3.5 U3.6 U3.12 U3.13 U3.14 U3.15 U3.16 U3.17 U3.18 U3.19 U3.20 U3.21 U3.22 U3.23 U4.3 U4.6 U4.8 U4.9 U4.10 U4.11 U4.12 U4.13 U4.14 U4.19 U4.22 U4.23 U4.24 U4.26 U4.27 U4.28 U5.1 U5.3 U5.5 U5.6 U5.7 U5.8 U5.10 U5.13 U5.14 U5.15 U7.2 U7.3 U7.4 U7.5 U7.9 U7.14 U8.2 U8.3 U8.4 U8.5 U8.6 U8.7 U8.14 U8.15 U9.1 U9.8 U9.Z1 U9.Z2 U9.Z3 U9.Z4 U10.7 U10.8 U11.1 U11.2 U11.9 U11.10 U11.11 U11.12 U11.13 U11.14 U11.19 U11.22 U11.23 U11.24 U11.26 U11.27 U11.28 U11.32 U12.1 W68.2

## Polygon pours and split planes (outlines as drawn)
VCC on Top Layer "Top Layer-No Net" (solid, pour order 44): 34.4,84.65 46.2,84.65 46.2,73.75 34.4,73.75 34.4,74.75
GND on Top Layer "Top Layer-No Net" (solid, pour order 42): 34.4,66.65 46.2,66.65 46.2,55.75 34.4,55.75 34.4,56.75
GND on Top Layer "Top Layer-No Net" (solid, pour order 40): 31.2,25.25 43,25.25 43,14.35 31.2,14.35 31.2,15.35
GND on Top Layer "Top Layer-No Net" (solid, pour order 38): 330.2,65.2 335.9,65.2 338.3,67.6 338.3,90.4 337.3,91.4 337.1,91.6 333.7,91.6 333.7,95.9 338.3,95.9 342,92.2 342,63.2 340,61.2 330.2,61.2
VCC on Top Layer "Top Layer-No Net" (solid, pour order 36): 327,84.95 333.7,84.95 333.7,74.05 327,74.05
VCC on Top Layer "Top Layer-No Net" (solid, pour order 34): 34.4,44.45 46.2,44.45 46.2,33.55 34.4,33.55 34.4,34.55
GND on Top Layer "Top Layer-No Net" (solid, pour order 32): 318.7,65.15 330.5,65.15 330.5,54.25 318.7,54.25 318.7,55.25
VCC on Top Layer "Top Layer-No Net" (solid, pour order 28): 189.8,16.4 188.5,16.4 187.4,17.5 186.6,17.5 183.9,20.2 183.9,22.2 183.9,23.9 189.2,23.9 189.8,23.9 189.8,20.1
3V3 on Top Layer "Top Layer-No Net" (solid, pour order 26): 191.5,17.2 192.5,17.2 193.6,16.1 196.5,16.1 196.7,16.3 198.2,16.3 198.2,14.5 198.2,8 189.5,8 189.5,10.5 192.8,13.8 192.8,15.1 192.8,15.4 192.1,16.1 191,16.1 191,17.2
GND on Top Layer "Top Layer-No Net" (solid, pour order 24): 206.2,14.5 196.7,24 191,24 191,18.3 192.4,18.3 193.7,17 199.3,17 199.3,14.5
GND on Top Layer "Top Layer-No Net" (solid, pour order 0): 34.4,95.9 34.4,91.6 35.9,91.6 333.7,91.6 333.7,95.9
VCC on Top Layer "Top Layer-No Net" (solid, remove dead copper, pour order 2): 31.22,83.7 31.22,88 32.72,88 330.52,88 330.52,83.7
VCC on Top Layer "Top Layer-No Net" (solid, pour order 4): 34.4,76.1 34.4,71.8 35.9,71.8 333.7,71.8 333.7,76.1
GND on Top Layer "Top Layer-No Net" (solid, remove dead copper, pour order 6): 31.22,63.9 31.22,68.2 32.72,68.2 330.52,68.2 330.52,63.9
VCC on Top Layer "Top Layer-No Net" (solid, remove dead copper, pour order 8): 31.22,44.1 31.22,48.4 32.72,48.4 330.52,48.4 330.52,44.1
GND on Top Layer "Top Layer-No Net" (solid, pour order 10): 34.4,56.3 34.4,52 35.9,52 333.7,52 333.7,56.3
GND on Top Layer "Top Layer-No Net" (solid, remove dead copper, pour order 12): 31.22,24.3 31.22,28.6 32.72,28.6 330.52,28.6 330.52,24.3
VCC on Top Layer "Top Layer-No Net" (solid, pour order 14): 34.4,36.5 34.4,32.2 35.9,32.2 333.7,32.2 333.7,36.5
GND on Top Layer "Top Layer-No Net" (solid, pour order 16): 34.4,16.7 34.4,12.4 35.9,12.4 128.7,12.4 128.7,16.7
VCC on Top Layer "Top Layer-No Net" (solid, remove dead copper, pour order 18): 31.22,4.5 31.22,8.8 32.72,8.8 128.7,8.8 128.7,4.5
GND on Top Layer "Top Layer-No Net" (solid, pour order 20): 204,16.7 204,12.4 340.3,12.4 340.3,16.7
VCC on Top Layer "Top Layer-No Net" (solid, remove dead copper, pour order 22): 200.3,4.5 200.3,8.8 330.52,8.8 330.52,4.5
GND on Bottom Layer "Top Layer-No Net" (solid, pour order 52): 192.3,26.93 196.6,26.93 196.6,22.83 196.6,22.73 192.3,22.73
VCC on Bottom Layer "Top Layer-No Net" (solid, pour order 50): 132.1,14.1 137.8,14.1 137.8,16.4 137.8,31.1 141.3,34.6 141.3,36.5 136.3,36.5 136.3,34.2 136.3,33.5 134.8,33.5 133.8,33.5 133.8,29.9 132,28.1 132,14.1
VCC on Bottom Layer "Top Layer-No Net" (solid, pour order 48): 306.6,74.6 311.6,74.6 311.6,72.5 311.6,69 322.7,57.9 325,55.6 325,44.2 317.6,44.2 317.6,52.1 318.9,53.4 318.9,57.3 317.5,58.7 308.3,58.7 306.6,60.4
GND on Bottom Layer "Top Layer-No Net" (solid, pour order 46): 42.55,62.6 34.4,62.6 34.4,98.2 39.9,98.2 39.9,93.9 37.65,91.65 37.65,87.9 39.9,85.65 39.9,81.5 42.55,78.85
VCC on Bottom Layer "Top Layer-No Net" (solid, pour order 30): 176.8,36.6 176.8,25.9 179.6,23.1 179.9,22.8 188.3,22.8 188.9,22.8 188.9,23.5 188.9,24.2 185.8,27.3 184.3,28.8 182.8,28.8 181.5,28.8 180.7,29.6 180.5,29.8 180.5,31.9 180.5,33.2 181.9,34.6 182.3,35 182.3,36.6
GND on Bottom Layer "Top Layer-No Net" (solid, pour order 54): 174.6,102 174.6,95.9 175.7,94.8 175.8,94.7 181,94.7 183.4,94.7 184.4,95.7 184.7,96 184.7,102
GND on Bottom Layer "Top Layer-No Net" (solid, pour order 56): 154.5,102.3 158.8,102.3 158.8,98.8 158.8,93.7 158.5,93.7 154.5,93.7 154.5,94.3

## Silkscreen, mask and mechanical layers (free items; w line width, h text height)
Top Overlay:
  text "fsocieTy" at 338.7,98.6 h4
  text "blueTooTh / LoRa / wifi / nfc / oLeD / Cherry mx" at 20.8,43.3 h2
Board outline:
  lines w0.1: 0,0.9 ccw(c4.587,0.9) 1.344,-2.344 2.939,-3.939 ccw(c5.5,-1.379) 5.5,-5 363.2,-5 ccw(c363.2,-1.379) 365.761,-3.939 367.356,-2.344 ccw(c364.113,0.9) 368.7,0.9 368.7,99.1 ccw(c364.113,99.1) 367.356,102.344 365.761,103.939 ccw(c363.2,101.379) 363.2,105 362.8,105 5.9,105 5.5,105 ccw(c5.5,101.379) 2.939,103.939 1.344,102.344 ccw(c4.587,99.1) 0,99.1 0,0.9
Dimensions Top:
  lines w0.15: 35.5,0.1 35.5,100.1 ; 329.7,1.4 329.7,101.4
Courtyard Top:
  lines w0.1: 23.9,3 23.9,10.6 ; 26.8,30.4 26.8,35.5 ; 27.7,46.4 27.7,50.2 ; 29,87.7 29,89.8 ; 31.4,66.4 31.4,70
Documentation:
  lines w0.1: 383.6,-119.71 463.252,-119.71 ; 414.5,-122.585 414.5,-119.66 414.5,-116.66 ; 441.652,-122.6 441.652,-119.675 441.652,-116.675 ; 450.652,-122.6 450.652,-119.775 450.652,-116.675 ; 561.841,282.2 561.841,285.3 561.841,288.4
  lines w0.127: -32.011,-57.18 -26.931,-57.18 ; -32.011,154.275 -26.931,154.275 ; -26.931,13.305 -32.011,13.305 -32.011,223.998 ; -26.931,18.385 -26.931,223.998 ; -21.903,292.197 356.609,292.197 ; 17.265,-127.665 17.265,-122.585 ; 17.265,287.117 17.265,292.197 ; 66.414,-127.665 66.414,-122.585 ; 66.414,287.117 66.414,292.197 ; 115.563,-127.665 115.563,-122.585 ; 115.563,287.117 115.563,292.197 ; 164.839,-127.665 164.839,-122.585 ; 164.839,287.117 164.839,292.197 ; 263.137,-127.665 263.137,-122.585 ; 263.137,287.117 263.137,292.197 ; 263.264,-122.585 242.309,-122.585 356.609,-122.585 ; 263.264,292.197 242.309,292.197 356.609,292.197 ; 312.286,-127.665 312.286,-122.585 ; 312.286,287.117 312.286,292.197 ; 361.562,-127.665 361.562,-122.585 ; 361.562,287.117 361.562,292.197 ; 442.461,-122.585 463.416,-122.585 463.416,-92.105 556.761,-92.105 ; 442.461,292.197 463.416,292.197 ; 459.86,-127.665 459.86,-122.585 ; 459.86,287.117 459.86,292.197 ; 463.416,-117.632 525.138,-117.632 ; 463.416,-112.298 525.138,-112.298 ; 463.416,-106.964 525.138,-106.964 ; 463.416,-98.074 556.761,-98.074 ; 476.37,-112.171 476.37,-106.964 ; 509.009,-127.665 509.009,-122.585 ; 509.009,287.117 509.009,292.197 ; 525.138,-122.585 525.138,-92.105 ; 556.761,-57.18 561.841,-57.18 ; 556.761,154.275 561.841,154.275 ; 556.761,287.1 556.761,223.998 ; 556.761,287.117 -26.931,287.117 -26.931,223.998 ; 561.841,-117.505 561.841,83.79 ; 561.841,13.305 556.761,13.305 556.761,223.998 ; 561.841,18.385 561.841,223.998 ; -32.011,83.79 -26.931,83.79 ; -32.011,83.79 -32.011,-127.665 561.841,-127.665 561.841,292.197 ; -32.011,83.79 -26.931,83.79 ; -32.011,223.998 -26.931,223.998 ; -32.011,223.998 -32.011,292.197 561.841,292.197 ; -32.011,223.998 -26.931,223.998 ; -26.931,83.79 -26.931,-122.585 356.609,-122.585 ; 356.609,-122.585 556.761,-122.585 556.761,83.79 ; 356.609,292.197 561.841,292.197 ; 556.761,83.79 561.841,83.79 ; 556.761,83.79 561.841,83.79 ; 556.761,223.998 561.841,223.998 ; 556.761,223.998 561.841,223.998 ; 561.841,223.998 561.841,292.197 ; 213.988,-127.665 213.988,-122.585 213.988,-127.665 ; 213.988,287.117 213.988,292.197 213.988,287.117 ; 410.711,-127.665 410.711,-122.585 410.711,-127.665 ; 410.711,287.117 410.711,292.197 410.711,287.117
  lines w0.2: 383.6,-122.5 383.6,-116.6 463.252,-116.6
  text "1" at -7.974,288.768 h1.78
  text "2" at 41.065,288.768 h1.78
  text "3" at 90.324,288.768 h1.78
  text "4" at 139.617,288.768 h1.78
  text "5" at 188.893,288.768 h1.78
  text "6" at 237.788,288.768 h1.78
  text "7" at 287.047,288.768 h1.78
  text "8" at 336.34,288.768 h1.78
  text "9" at 385.616,288.768 h1.78
  text "10" at 434.511,288.768 h1.78
  text "11" at 483.77,288.768 h1.78
  text "12" at 533.063,288.768 h1.78
  text "A" at -30.106,256.815 h1.78
  text "A" at 558.666,256.815 h1.78
  text "B" at -30.106,187.219 h1.78
  text "B" at 558.666,187.219 h1.78
  text "C" at -30.106,116.607 h1.78
  text "C" at 558.666,116.607 h1.78
  text "D" at -30.106,46.249 h1.78
  text "D" at 558.666,46.249 h1.78
  text "E" at -30.106,-24.363 h1.78
  text "E" at 558.666,-24.363 h1.78
  text "F" at -30.106,-94.467 h1.78
  text "F" at 558.666,-94.467 h1.78
  text "ENGINEER:" at 527.932,-95.915 h1.14
  text "Anonymous" at 537.203,-95.915 h1.78
  text "CUSTOMER:" at 465.321,-96.042 h1.14
  text "?Customer" at 475.354,-96.042 h1.78
  text "TITLE:" at 465.321,-103.662 h1.14
  text "?Design name" at 470.401,-103.789 h1.78
  text "SIZE:" at 464.94,-110.393 h1.14
  text "A2" at 469.893,-110.393 h1.78
  text "NUMBER:" at 479.418,-110.393 h1.14
  text "??.???" at 487.292,-110.393 h1.78
  text "NAME:" at 501.111,-110.393 h1.14
  text "??_???" at 507.08,-110.393 h1.78
  text "DATE:" at 465.067,-115.346 h1.14
  text "REVISION:" at 501.111,-115.346 h1.14
  text "dd-mm-yyyy" at 470.274,-115.473 h1.78
  text "??" at 509.382,-115.473 h1.78
  text "Mechanical drawing" at 415.152,-118.675 h1.5
  text "DATE" at 454.252,-118.9 h1.5
  text "REV" at 443.852,-119 h1.5
  text "FILE NAME:" at 465.194,-120.553 h1.14
  text ".Pcb_File_Name_No_Path" at 474.338,-120.68 h1.78
  text "Customer reference" at 386,-121.8 h1.5
  text "NA" at 421.252,-121.875 h1.5
  text "-" at 451.752,-121.9 h1.5
  text "-" at 445.552,-121.975 h1.5
  text "1" at -7.974,-126.014 h1.78
  text "2" at 41.065,-126.014 h1.78
  text "3" at 90.324,-126.014 h1.78
  text "4" at 139.617,-126.014 h1.78
  text "5" at 188.893,-126.014 h1.78
  text "6" at 237.788,-126.014 h1.78
  text "7" at 287.047,-126.014 h1.78
  text "8" at 336.34,-126.014 h1.78
  text "9" at 385.616,-126.014 h1.78
  text "10" at 434.511,-126.014 h1.78
  text "11" at 483.77,-126.014 h1.78
  text "12" at 533.063,-126.014 h1.78
Drill Drawing:
  circle w0.254: c77.486,133.908 r0.847
  circle w0.254: c77.486,130.098 r0.508
  circle w0.254: c77.486,130.098 r0.847
  lines w0.254: 76.639,138.564 78.332,138.564 77.486,136.871 76.639,138.564 ; 76.639,141.104 77.062,141.104 77.486,140.681 77.909,141.104 78.332,141.104 77.909,141.528 78.332,141.951 77.909,141.951 77.486,142.374 77.062,141.951 76.639,141.951 77.062,141.528 76.639,141.104 ; 76.639,144.491 77.486,144.914 78.332,144.491 77.909,145.338 78.332,146.184 77.486,145.761 76.639,146.184 77.062,145.338 76.639,144.491 ; 76.639,149.148 77.486,148.301 78.332,149.148 77.486,149.994 76.639,149.148 ; 76.639,152.111 78.332,152.111 78.332,153.804 76.639,153.804 76.639,152.111 ; 76.639,155.921 78.332,155.921 78.332,157.614 76.639,157.614 76.639,155.921 ; 76.639,160.154 77.062,160.154 77.062,159.731 77.909,159.731 77.909,160.154 78.332,160.154 78.332,161.001 77.909,161.001 77.909,161.424 77.062,161.424 77.062,161.001 76.639,161.001 76.639,160.154 ; 76.639,163.541 76.639,163.964 77.062,164.388 76.639,164.811 76.639,165.234 77.062,165.234 77.486,164.811 77.909,165.234 78.332,165.234 78.332,164.811 77.909,164.388 78.332,163.964 78.332,163.541 77.909,163.541 77.486,163.964 77.062,163.541 76.639,163.541 ; 76.978,156.26 77.994,156.26 77.994,157.276 76.978,157.276 76.978,156.26
  lines w0.381: 75.12,128.108 273.846,128.108 ; 75.12,166.208 273.846,166.208 ; 89.112,124.298 89.112,170.018 ; 104.095,124.298 104.095,170.018 ; 132.788,124.298 132.788,170.018 ; 145.637,124.298 145.637,170.018 ; 164.276,124.298 164.276,170.018 ; 202.365,124.298 202.365,170.018 ; 217.347,124.298 217.347,170.018 ; 245.025,124.298 245.025,170.018 ; 75.12,124.298 273.846,124.298 273.846,170.018 75.12,170.018 75.12,124.298
  text "Symbol" at 77.406,167.351 h1.83
  text "Count" at 90.255,167.351 h1.83
  text "Hole Size" at 105.238,167.351 h1.83
  text "Plated" at 133.931,167.351 h1.83
  text "Hole Type" at 146.78,167.351 h1.83
  text "Drill Layer Pair" at 165.419,167.351 h1.83
  text "Via/Pad" at 203.508,167.351 h1.83
  text "Pad Shape" at 218.49,167.351 h1.83
  text "Technology" at 246.168,167.351 h1.83
  text "2" at 90.255,163.541 h1.52
  text "25.59mil (0.650mm)" at 105.238,163.541 h1.52
  text "PTH" at 133.931,163.541 h1.52
  text "Slot" at 146.78,163.541 h1.52
  text "Top Layer - Bottom Layer" at 165.419,163.541 h1.52
  text "Pad" at 203.508,163.541 h1.52
  text "Rounded" at 218.49,163.541 h1.52
  text "r125_85h65_85r100" at 246.168,163.541 h1.52
  text "2" at 90.255,159.731 h1.52
  text "32.48mil (0.825mm)" at 105.238,159.731 h1.52
  text "PTH" at 133.931,159.731 h1.52
  text "Slot" at 146.78,159.731 h1.52
  text "Top Layer - Bottom Layer" at 165.419,159.731 h1.52
  text "Pad" at 203.508,159.731 h1.52
  text "Rounded" at 218.49,159.731 h1.52
  text "c0h82_150" at 246.168,159.731 h1.52
  text "5" at 90.255,155.921 h1.52
  text "118.11mil (3.000mm)" at 105.238,155.921 h1.52
  text "PTH" at 133.931,155.921 h1.52
  text "Round" at 146.78,155.921 h1.52
  text "Top Layer - Bottom Layer" at 165.419,155.921 h1.52
  text "Pad" at 203.508,155.921 h1.52
  text "Rounded" at 218.49,155.921 h1.52
  text "r137_300h300r100" at 246.168,155.921 h1.52
  text "6" at 90.255,152.111 h1.52
  text "40.16mil (1.020mm)" at 105.238,152.111 h1.52
  text "PTH" at 133.931,152.111 h1.52
  text "Round" at 146.78,152.111 h1.52
  text "Top Layer - Bottom Layer" at 165.419,152.111 h1.52
  text "Pad" at 203.508,152.111 h1.52
  text "(Mixed)" at 218.49,152.111 h1.52
  text "(Mixed)" at 246.168,152.111 h1.52
  text "8" at 90.255,148.301 h1.52
  text "53.15mil (1.350mm)" at 105.238,148.301 h1.52
  text "PTH" at 133.931,148.301 h1.52
  text "Round" at 146.78,148.301 h1.52
  text "Top Layer - Bottom Layer" at 165.419,148.301 h1.52
  text "Pad" at 203.508,148.301 h1.52
  text "Rounded Rectangle" at 218.49,148.301 h1.52
  text "r170_225h135r50" at 246.168,148.301 h1.52
  text "25" at 90.255,144.491 h1.52
  text "43.31mil (1.100mm)" at 105.238,144.491 h1.52
  text "PTH" at 133.931,144.491 h1.52
  text "Round" at 146.78,144.491 h1.52
  text "Top Layer - Bottom Layer" at 165.419,144.491 h1.52
  text "Pad" at 203.508,144.491 h1.52
  text "Rounded Rectangle" at 218.49,144.491 h1.52
  text "(Mixed)" at 246.168,144.491 h1.52
  text "62" at 90.255,140.681 h1.52
  text "161.42mil (4.100mm)" at 105.238,140.681 h1.52
  text "PTH" at 133.931,140.681 h1.52
  text "Round" at 146.78,140.681 h1.52
  text "Top Layer - Bottom Layer" at 165.419,140.681 h1.52
  text "Pad" at 203.508,140.681 h1.52
  text "Rounded Rectangle" at 218.49,140.681 h1.52
  text "s0h410r25" at 246.168,140.681 h1.52
  text "124" at 90.255,136.871 h1.52
  text "70.87mil (1.800mm)" at 105.238,136.871 h1.52
  text "PTH" at 133.931,136.871 h1.52
  text "Round" at 146.78,136.871 h1.52
  text "Top Layer - Bottom Layer" at 165.419,136.871 h1.52
  text "Pad" at 203.508,136.871 h1.52
  text "Rounded Rectangle" at 218.49,136.871 h1.52
  text "s0h180r25" at 246.168,136.871 h1.52
  text "132" at 90.255,133.061 h1.52
  text "62.99mil (1.600mm)" at 105.238,133.061 h1.52
  text "PTH" at 133.931,133.061 h1.52
  text "Round" at 146.78,133.061 h1.52
  text "Top Layer - Bottom Layer" at 165.419,133.061 h1.52
  text "Pad" at 203.508,133.061 h1.52
  text "(Mixed)" at 218.49,133.061 h1.52
  text "(Mixed)" at 246.168,133.061 h1.52
  text "275" at 90.255,129.251 h1.52
  text "13.78mil (0.350mm)" at 105.238,129.251 h1.52
  text "PTH" at 133.931,129.251 h1.52
  text "Round" at 146.78,129.251 h1.52
  text "Top Layer - Bottom Layer" at 165.419,129.251 h1.52
  text "Via" at 203.508,129.251 h1.52
  text "Rounded" at 218.49,129.251 h1.52
  text "v80h35m0mx0" at 246.168,129.251 h1.52
  text "641 Total" at 90.255,125.441 h1.52
  text "Slot definitions :" at 77.406,121.759 h1.52
  text "Routed Path Length" at 103.637,121.759 h1.52
  text "= Calculated from tool start centre position to tool end centre position." at 131.644,121.759 h1.52
  text "Hole Length" at 103.637,119.219 h1.52
  text "= Routed Path Length + Tool Size = Slot length as defined in the PCB layout" at 121.234,119.219 h1.52

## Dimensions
35.5,0.1 to 329.7,1.4 on Board outline
363.2,-5 to 362.8,105 on Dimensions Top
0,99.1 to 368.7,99.1 on Dimensions Top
